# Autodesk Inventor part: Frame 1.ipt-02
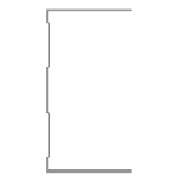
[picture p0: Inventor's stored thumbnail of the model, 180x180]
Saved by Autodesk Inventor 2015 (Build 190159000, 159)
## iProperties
Created: 2015-04
Part Number: Frame 1.ipt-02
Material: Aluminum 6061
Description: Kévin Novo
Document SubType Name: Modeling
Standard: Kevin
Designer: suporte
Standards Organization: Kevin
Language: en-US
Size Designation: (Unnamed 2)
Categories: <MemberInstance><Categories><Category DisplayName="Structural Shapes" InternalName="089c4875-fa83-4c05-b084-43b9cc11f5ed" Mnemonic="GRDR"><CategoryParameter Dis
Density: 2.7 g/cm^3
Appearance: Aluminum - Flat
IsCustomPart: 1
G_W: 50,000 mm
G_H: 75,000 mm
G_L: 742,325 mm
+371032C4-853D-4D1C-9F66-73CC0C0069CB+CUTDETAIL1: Cut
+9BC56BD3-3601-4756-9CD3-DFE412EE9504+CUTDETAIL2: Miter 67,51 deg
_CCFamilyMember: 2
_CCFamilyDisplayName: Kévin - Kévin Novo
_FrameMemberDoc: Frame Member File
_Version: 15.0.0
_GetPNFromCC: 1
Author: suporte
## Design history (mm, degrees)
node "Start Plane"
node "End Plane"
sketch "Sketch"
  geometry: L1 (24.7, 37.5)-(24.7, 36.9); L2 (24.7, 36.9)-(-24.7, 36.9); L3 (-24.7, -36.9)-(24.7, -36.9); L4 (24.7, -36.9)-(24.7, -37.5); L5 (24.7, -37.5)-(-25.3, -37.5); L6 (-25.3, 37.5)-(24.7, 37.5); L7 (-24.7, 36.9)-(-24.7, 31.9); L8 (-24.7, 31.9)-(-23.3, 30.5); L9 (-23.3, 30.5)-(-23.3, 10.934); L10 (-23.3, 10.934)-(-24.7, 9.534); L11 (-24.7, 9.534)-(-24.7, -9.534); L12 (-24.7, -9.534)-(-23.3, -10.934); L13 (-23.3, -10.934)-(-23.3, -30.5); L14 (-23.3, -30.5)-(-24.7, -31.9); L15 (-24.7, -31.9)-(-24.7, -36.9); L16 (-25.3, -37.5)-(-25.3, -31.651); L17 (-25.3, -31.651)-(-23.9, -30.251); L18 (-23.9, -30.251)-(-23.9, -11.183); L19 (-23.9, -11.183)-(-25.3, -9.783); L20 (-25.3, -9.783)-(-25.3, 9.783); L21 (-25.3, 9.783)-(-23.9, 11.183); L22 (-23.9, 11.183)-(-23.9, 30.251); L23 (-23.9, 30.251)-(-25.3, 31.651); L24 (-25.3, 31.651)-(-25.3, 37.5); L25 (-25.3, 0)-(30.37, 0); 3 further points
  constraints: 50 end point, 10 point on line, 9 parallel, 5 perpendicular, 4 equal length, 3 midpoint, 3 vertical, 2 vertical alignment, 1 collinear, 1 horizontal, 1 horizontal alignment
  dimensions: "d3" = 0.6 distance of L1.start L1.end (= d6); "d5" = 75 distance between parallel lines of L5 L6; "d6" = 0.6 distance between parallel lines of L24 L7 (= d8); "d7" = 0.6 distance between parallel lines of L8 L23 (= d8); "d8" = 0.6 distance between parallel lines of L22 L9 (= d12); "Espessura" = 0.6 distance between parallel lines of L17 L14; "d10" = 0.6 distance between parallel lines of L13 L18 (= Espessura); "d11" = 0.6 distance between parallel lines of L12 L19 (= Espessura); "d12" = 0.6 distance between parallel lines of L21 L10 (= d11); "d13" = 5 distance of L2.end L7.end; "d15" = 135 deg angle of L9 L8; "d16" = 2 distance between parallel lines of L24 L9; "d17" = 50 distance of L6.start L1.start
extrude "Body" join sketch "Sketch" stored distance "d24" = 0.13; taper "d25" = 0 deg
node "Driven Length"
  sketch "Sketch10"
    geometry: L1 (0, 0)-(10, 0) reference
    constraints: 2 end point, 1 horizontal
  workplane "Work Plane7"
  sketch "Sketch11"
    geometry: L1 (-2, 12.5)-(12, 12.5) reference; L2 (-2, 754.825)-(12, 754.825) reference
    dimensions: "d27" = 742.32488 distance between parallel lines of L1 L2 (derived)
workplane "Work Plane8"
split "Split1"
workplane "Work Plane9"
split "Split2"
body "Solid1"
other parameters: "tamanho" = 718.59902, "G_OFFSET_START" = -12.5 [user parameter; used in 1 equation term], "G_OFFSET_END" = 36.22585 [user parameter; used in 1 equation term], "d22" = 12.5 (= -G_OFFSET_START), "d23" = 754.82488 (= tamanho + G_OFFSET_END), "G_L" = 742.32488 (= d27) [user parameter], "d34" = 90 deg
